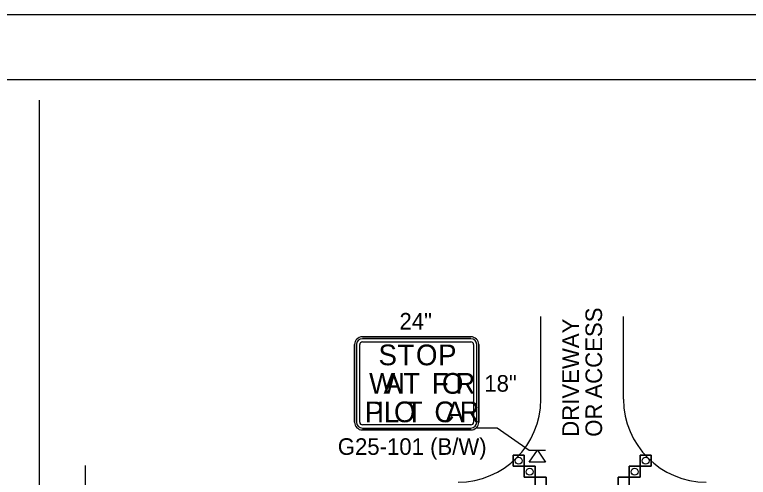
# Model space of a CAD drawing. Extents: x 99999.1 to 100095.7, y 99995 to 100010.7.
# Drawn here: x 100070.382 to 100073.928, y 100008.454 to 100010.687 of the extents above; entities that cross this region are included whole.
import ezdxf

# ---------------------------------------------------------------- set-up
doc = ezdxf.new("R2010")
doc.units = 0
for name, color, linetype in [('RD_ED_DrivewayEdge', 7, 'Continuous'), ('SH_GI_PlotLimits', 7, 'Continuous'), ('SH_GI_SheetBorder', 7, 'Continuous'), ('TR_SN_ConstructionSigns', 7, 'Continuous'), ('TR_WZ_PortableSignMountBlk-Wht', 7, 'Continuous'), ('TR_WZ_TrafficCone', 7, 'Continuous'), ('TR_WZ_WorkZoneDetails', 7, 'Continuous'), ('TR_WZ_WorkZoneTextCurrent', 7, 'Continuous')]:
    doc.layers.add(name, color=color, linetype=linetype)

msp = doc.modelspace()

# ---------------------------------------------------------------- linework, layer by layer
at = {"layer": 'RD_ED_DrivewayEdge'}
for p, q in [((100072.925, 100008.8304), (100072.925, 100009.2305)), ((100073.325, 100008.8304), (100073.325, 100009.2305))]:
    msp.add_line(p, q, dxfattribs=at)
for centre, start, end in [((100072.525, 100008.8304), 270, 0), ((100073.725, 100008.8304), 180, 270)]:
    msp.add_arc(centre, 0.4, start, end, dxfattribs=at)
at = {"layer": 'SH_GI_PlotLimits'}
msp.add_lwpolyline([(100059.0625, 99999.6875), (100076.0625, 99999.6875), (100076.0625, 100010.6875), (100059.0625, 100010.6875)], close=True, dxfattribs=at)
at = {"layer": 'SH_GI_SheetBorder'}
msp.add_line((100060, 100010.375), (100075.75, 100010.375), dxfattribs=at)
at = {"layer": 'TR_SN_ConstructionSigns'}
for p, q in [((100072.0625, 100009.1323), (100072.5875, 100009.1323)), ((100072.5875, 100009.1323), (100072.0625, 100009.1323)), ((100072.5875, 100009.1323), (100072.0625, 100009.1323)), ((100072.5875, 100009.1229), (100072.0625, 100009.1229)), ((100072.0625, 100009.1073), (100072.5875, 100009.1073)), ((100072.025, 100008.7198), (100072.025, 100009.0948)), ((100072.025, 100009.0948), (100072.025, 100008.7198)), ((100072.025, 100009.0948), (100072.025, 100008.7198)), ((100072.0344, 100009.0948), (100072.0344, 100008.7198)), ((100072.05, 100008.7198), (100072.05, 100009.0948)), ((100072.6, 100009.0948), (100072.6, 100008.7198)), ((100072.6156, 100008.7198), (100072.6156, 100009.0948)), ((100072.625, 100009.0948), (100072.625, 100008.7198)), ((100072.625, 100008.7198), (100072.625, 100009.0948)), ((100072.625, 100008.7198), (100072.625, 100009.0948)), ((100072.5875, 100008.7073), (100072.0625, 100008.7073)), ((100072.0625, 100008.6916), (100072.5875, 100008.6916)), ((100072.5875, 100008.6823), (100072.0625, 100008.6823)), ((100072.0625, 100008.6823), (100072.5875, 100008.6823)), ((100072.0625, 100008.6823), (100072.5875, 100008.6823))]:
    msp.add_line(p, q, dxfattribs=at)
for centre, radius, start, end in [((100072.0625, 100009.0948), 0.0375, 90, 180), ((100072.0625, 100009.0948), 0.0375, 90, 180), ((100072.0625, 100009.0948), 0.0375, 90, 180), ((100072.0625, 100009.0948), 0.0281, 90, 180), ((100072.0625, 100009.0948), 0.0125, 90, 180), ((100072.5875, 100009.0948), 0.0375, 0, 90), ((100072.5875, 100009.0948), 0.0375, 0, 90), ((100072.5875, 100009.0948), 0.0375, 0, 90), ((100072.5875, 100009.0948), 0.0281, 0, 90), ((100072.5875, 100009.0948), 0.0125, 0, 90), ((100072.0625, 100008.7198), 0.0375, 180, 270), ((100072.0625, 100008.7198), 0.0375, 180, 270), ((100072.0625, 100008.7198), 0.0375, 180, 270), ((100072.0625, 100008.7198), 0.0281, 180, 270), ((100072.0625, 100008.7198), 0.0125, 180, 270), ((100072.5875, 100008.7198), 0.0375, 270, 0), ((100072.5875, 100008.7198), 0.0375, 270, 0), ((100072.5875, 100008.7198), 0.0281, 270, 0), ((100072.5875, 100008.7198), 0.0125, 270, 0), ((100072.5875, 100008.7198), 0.0375, 270, 0)]:
    msp.add_arc(centre, radius, start, end, dxfattribs=at)
at = {"layer": 'TR_WZ_PortableSignMountBlk-Wht'}
msp.add_line((100072.8683, 100008.5846), (100072.9483, 100008.5846), dxfattribs=at)
msp.add_lwpolyline([(100072.9083, 100008.5846), (100072.9483, 100008.5271), (100072.8683, 100008.5271)], close=True, dxfattribs=at)
at = {"layer": 'TR_WZ_TrafficCone'}
for points in [[(100072.7917, 100008.5605), (100072.845, 100008.5605), (100072.845, 100008.5071), (100072.7917, 100008.5071), (100072.7917, 100008.5605)], [(100072.7917, 100008.5071), (100072.845, 100008.5071), (100072.845, 100008.5605), (100072.7917, 100008.5605), (100072.7917, 100008.5071)], [(100073.405, 100008.5605), (100073.4583, 100008.5605), (100073.4583, 100008.5071), (100073.405, 100008.5071), (100073.405, 100008.5605)], [(100073.405, 100008.5071), (100073.4583, 100008.5071), (100073.4583, 100008.5605), (100073.405, 100008.5605), (100073.405, 100008.5071)], [(100072.845, 100008.5071), (100072.8984, 100008.5071), (100072.8984, 100008.4538), (100072.845, 100008.4538), (100072.845, 100008.5071)], [(100072.845, 100008.4538), (100072.8984, 100008.4538), (100072.8984, 100008.5071), (100072.845, 100008.5071), (100072.845, 100008.4538)], [(100073.3516, 100008.5071), (100073.405, 100008.5071), (100073.405, 100008.4538), (100073.3516, 100008.4538), (100073.3516, 100008.5071)], [(100073.3516, 100008.4538), (100073.405, 100008.4538), (100073.405, 100008.5071), (100073.3516, 100008.5071), (100073.3516, 100008.4538)], [(100072.8984, 100008.4538), (100072.9517, 100008.4538), (100072.9517, 100008.4005), (100072.8984, 100008.4005), (100072.8984, 100008.4538)], [(100072.8984, 100008.4005), (100072.9517, 100008.4005), (100072.9517, 100008.4538), (100072.8984, 100008.4538), (100072.8984, 100008.4005)], [(100073.2983, 100008.4538), (100073.3516, 100008.4538), (100073.3516, 100008.4005), (100073.2983, 100008.4005), (100073.2983, 100008.4538)], [(100073.2983, 100008.4005), (100073.3516, 100008.4005), (100073.3516, 100008.4538), (100073.2983, 100008.4538), (100073.2983, 100008.4005)]]:
    msp.add_lwpolyline(points, dxfattribs=at)
for centre in [(100072.8184, 100008.5338), (100073.4316, 100008.5338), (100072.8717, 100008.4805), (100073.3783, 100008.4805)]:
    msp.add_circle(centre, 0.0167, dxfattribs=at)
at = {"layer": 'TR_WZ_WorkZoneDetails'}
for p, q in [((100070.5, 100010.275), (100070.5, 100001.6859)), ((100072.614, 100008.6933), (100072.714, 100008.6933)), ((100072.714, 100008.6933), (100072.8683, 100008.5846))]:
    msp.add_line(p, q, dxfattribs=at)
msp.add_lwpolyline([(100070.725, 100006.5904), (100070.725, 100007.473), (100070.645, 100007.473), (100070.805, 100007.6279), (100070.725, 100007.6279), (100070.725, 100008.5105)], dxfattribs=at)

# ---------------------------------------------------------------- texts
at = {"layer": 'TR_SN_ConstructionSigns'}
for s, p in [('24"', (100072.2419, 100009.1673)), ('18"', (100072.6519, 100008.8673)), ('G25-101 (B/W)', (100071.9438, 100008.5623))]:
    msp.add_text(s, height=0.08, rotation=360, dxfattribs=at).set_placement(p)
for s, p in [('S', (100072.1405, 100008.9948)), ('T', (100072.2325, 100008.9948)), ('O', (100072.3215, 100008.9948)), ('P', (100072.4285, 100008.9948)), ('W', (100072.095, 100008.8573)), ('A', (100072.165, 100008.8573)), ('I', (100072.233, 100008.8573)), ('T', (100072.26, 100008.8573)), ('F', (100072.398, 100008.8573)), ('O', (100072.447, 100008.8573)), ('R', (100072.512, 100008.8573)), ('P', (100072.0745, 100008.7198)), ('I', (100072.1315, 100008.7198)), ('L', (100072.1665, 100008.7198)), ('O', (100072.2155, 100008.7198)), ('T', (100072.2725, 100008.7198)), ('C', (100072.4105, 100008.7198)), ('A', (100072.4645, 100008.7198)), ('R', (100072.5325, 100008.7198))]:
    msp.add_text(s, height=0.1, dxfattribs=at).set_placement(p)
at = {"layer": 'TR_WZ_WorkZoneTextCurrent'}
for s, p in [('ACCESS', (100073.221, 100008.8338)), ('DRIVEWAY', (100073.109, 100008.6495)), ('OR', (100073.221, 100008.6495))]:
    msp.add_text(s, height=0.08, rotation=90, dxfattribs=at).set_placement(p)

doc.saveas('drawing.dxf')
